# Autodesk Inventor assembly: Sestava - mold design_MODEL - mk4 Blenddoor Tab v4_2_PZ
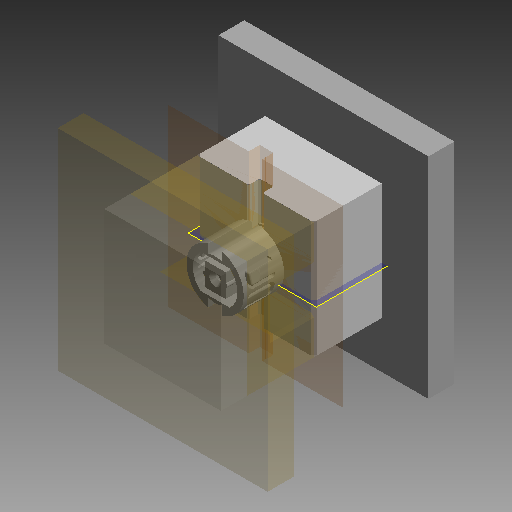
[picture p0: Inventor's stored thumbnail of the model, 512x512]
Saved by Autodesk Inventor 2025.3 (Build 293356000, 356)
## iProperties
Part Number: Sestava - mold design_MODEL - mk4 Blenddoor Tab v4_2_PZ
Document SubType Name: Sestava
Designer: Patrik
Author: Patrik
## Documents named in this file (5)
- C:\Users\Patrik\Documents\Skola\Bakalarska prace\Prakticka cast\Sestava - mold design_MODEL - mk4 Blenddoor Tab v4_2_PZ.iam
- C:\Users\Patrik\Documents\Skola\Bakalarska prace\Prakticka cast\Sestava - mold design_MODEL - mk4 Blenddoor Tab v4_2_MP.ipt
- C:\Users\Patrik\Documents\Skola\Bakalarska prace\Prakticka cast\Sestava - mold design_MODEL - mk4 Blenddoor Tab v4_2_WP.ipt
- C:\Users\Patrik\Documents\Skola\Bakalarska prace\Prakticka cast\Sestava - mold design_MODEL - mk4 Blenddoor Tab v4_2_CR_Base.ipt
- C:\Users\Patrik\Documents\Skola\Bakalarska prace\Prakticka cast\Sestava - mold design_MODEL - mk4 Blenddoor Tab v4_2_CV_Base.ipt
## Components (4 placed, 4 different names)
1. Sestava - mold design_MODEL - mk4 Blenddoor Tab v4_2_MP:1 — Stejný směr:1, Stejný směr:2, Stejný směr:3, Stejný směr:4, Stejný směr:5, Stejný směr:6, Stejný směr:13
2. Sestava - mold design_MODEL - mk4 Blenddoor Tab v4_2_WP:1 — Stejný směr:4, Stejný směr:5, Stejný směr:6
3. Sestava - mold design_MODEL - mk4 Blenddoor Tab v4_2_CR_Base:1 — Stejný směr:7, Stejný směr:8, Stejný směr:9, Stejný směr:13, Proti sobě:1
4. Sestava - mold design_MODEL - mk4 Blenddoor Tab v4_2_CV_Base:1 — Stejný směr:10, Stejný směr:11, Stejný směr:12, Proti sobě:1
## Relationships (14: Flush 13, Mate 1)
- Stejný směr:1 [Flush]: Sestava - mold design_MODEL - mk4 Blenddoor Tab v4_2_MP:1
- Stejný směr:2 [Flush]: Sestava - mold design_MODEL - mk4 Blenddoor Tab v4_2_MP:1
- Stejný směr:3 [Flush]: Sestava - mold design_MODEL - mk4 Blenddoor Tab v4_2_MP:1
- Stejný směr:4 [Flush]: Sestava - mold design_MODEL - mk4 Blenddoor Tab v4_2_MP:1 ↔ Sestava - mold design_MODEL - mk4 Blenddoor Tab v4_2_WP:1
- Stejný směr:5 [Flush]: Sestava - mold design_MODEL - mk4 Blenddoor Tab v4_2_MP:1 ↔ Sestava - mold design_MODEL - mk4 Blenddoor Tab v4_2_WP:1
- Stejný směr:6 [Flush]: Sestava - mold design_MODEL - mk4 Blenddoor Tab v4_2_MP:1 ↔ Sestava - mold design_MODEL - mk4 Blenddoor Tab v4_2_WP:1
- Stejný směr:7 [Flush]: Sestava - mold design_MODEL - mk4 Blenddoor Tab v4_2_CR_Base:1
- Stejný směr:8 [Flush]: Sestava - mold design_MODEL - mk4 Blenddoor Tab v4_2_CR_Base:1
- Stejný směr:9 [Flush]: Sestava - mold design_MODEL - mk4 Blenddoor Tab v4_2_CR_Base:1
- Stejný směr:10 [Flush]: Sestava - mold design_MODEL - mk4 Blenddoor Tab v4_2_CV_Base:1
- Stejný směr:11 [Flush]: Sestava - mold design_MODEL - mk4 Blenddoor Tab v4_2_CV_Base:1
- Stejný směr:12 [Flush]: Sestava - mold design_MODEL - mk4 Blenddoor Tab v4_2_CV_Base:1
- Stejný směr:13 [Flush]: Sestava - mold design_MODEL - mk4 Blenddoor Tab v4_2_MP:1 ↔ Sestava - mold design_MODEL - mk4 Blenddoor Tab v4_2_CR_Base:1
- Proti sobě:1 [Mate]: Sestava - mold design_MODEL - mk4 Blenddoor Tab v4_2_CR_Base:1 ↔ Sestava - mold design_MODEL - mk4 Blenddoor Tab v4_2_CV_Base:1
